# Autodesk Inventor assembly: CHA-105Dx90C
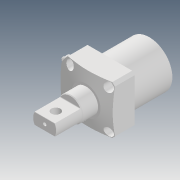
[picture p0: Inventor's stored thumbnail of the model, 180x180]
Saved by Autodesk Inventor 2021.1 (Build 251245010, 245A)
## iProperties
Created: 2019-12
Part Number: CHA-105Dx90C
Description: STEP AP203
Document SubType Name: Assembly
Designer: user
Title: CHA-105Dx90C.STEP
Revision Number: ÈÎºÎ
Sending System: SolidWorks 2017
Preprocessor: SwSTEP 2.0
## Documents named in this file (5)
- D:\Vault_2016\Projekty\Clamptek\Hydraulic\CHA\CHA\CHA-105\Inventor\CHA-105Dx90C\CHA-105Dx90C.iam
- D:\Vault_2016\Projekty\Clamptek\Hydraulic\CHA\CHA\CHA-105\Inventor\CHA-105Dx90C\CHA-90±¾Ìå.ipt
- D:\Vault_2016\Projekty\Clamptek\Hydraulic\CHA\CHA\CHA-105\Inventor\CHA-105Dx90C\CHA-105D»îÈû¸Ë.ipt
- D:\Vault_2016\Projekty\Clamptek\Hydraulic\CHA\CHA\CHA-105\Inventor\CHA-105Dx90C\CZL30µ÷ËÙ·§.ipt
- D:\Vault_2016\Projekty\Clamptek\Hydraulic\CHA\CHA\CHA-105\Inventor\CHA-105Dx90C\G3-8¶ÂÍ·.ipt
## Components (4 placed, 4 different names)
1. CHA-90±¾Ìå_1
2. CHA-105D»îÈû¸Ë_2
3. CZL30µ÷ËÙ·§_3
4. G3-8¶ÂÍ·_4
